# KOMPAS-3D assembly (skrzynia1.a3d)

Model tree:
1. X Axis
2. Y Axis
3. Z Axis
4. Origin  (labels: D:\Program Files\ASCON\KOMPAS-3D V10\Sys\GRAPHIC_EN.LYT; skrzynia1.spw; H:\00_Work\Webinars\09_06_10_BOM\My sample\skrzynia1.spw)
     Orientation = 1

Referenced files in H:\00_Work\Webinars\09_06_10_BOM\My sample\: Base plate.a3d, Side plate.a3d, Front_plate.a3d, Top_plate.a3d, skrzynia1.spw
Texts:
  phr220400
  Wood (15% moisture content)
  Three Point Plane
  Plane at Angle
  Line and Point Plane
  Axis through Two Vertices
  Axis of Feature
  Axis of Conical Surface
  Axis through Edge
  Trim by Surface
  Trim by Sketch
  Intersection Axis of Two Planes
  Two Line Plane
  Line and Face Plane
  Pattern by Sample
  Point in CM
  Feature with No History
  Linear Dimension from Line to Point
  Surface Finish Symbol
  Geometric Tolerance Symbol
  Leader #1
  Leader #2
  Leader #3
  Shape Deviations and Datum
  Node point number
  Mark of coordination axis
  Node point designation
  Mark/Reference designation with leader
  Mark/reference designation on line
  Mark/Reference designation without leader
  Plate 00
  Plate of side
  Plate 03
  Plate 04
